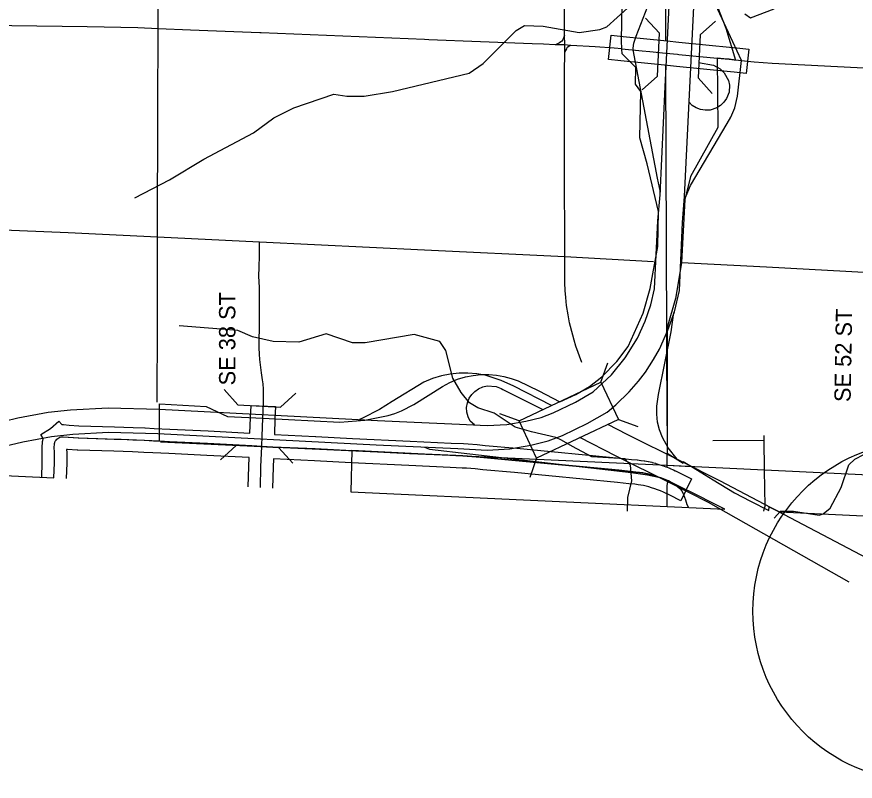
# Model space of a CAD drawing. Extents: x -1403959 to 81668, y -1400582 to 11018.
# Drawn here: x 7536.2 to 7735.1, y 7653.3 to 7834.6 of the extents above; entities that cross this region are included whole.
import ezdxf

# ---------------------------------------------------------------- set-up
doc = ezdxf.new("R2010")
doc.units = 0
for name, color, linetype in [('tdCiCityStreetTxt', 7, 'Continuous'), ('tdCiCoBndryTxt', 7, 'Continuous'), ('tdCiMapCityName', 7, 'Continuous'), ('tdCiMapFrame', 7, 'Continuous'), ('tdCiRRCL', 7, 'Continuous'), ('tdCiRROwnerTxt', 7, 'Continuous'), ('tdCiSectLine', 7, 'Continuous'), ('tdCiSectNmbr', 7, 'Continuous'), ('tdCiSectTwpRng', 7, 'Continuous'), ('tdCiUABTitleFrame', 7, 'Continuous'), ('tdCoCityStreetMajor', 7, 'Continuous'), ('tdCoCityStreetMinor', 7, 'Continuous'), ('tdCoClipBndry', 7, 'Continuous'), ('tdCoDivCarto', 7, 'Continuous'), ('tdCoIntCL', 7, 'Continuous'), ('tdCoSectNmbr', 7, 'Continuous'), ('tdCoSurfAsphalt', 7, 'Continuous'), ('tdCoSurfBitum', 7, 'Continuous'), ('tdCoSurfEarth', 7, 'Continuous')]:
    doc.layers.add(name, color=color, linetype=linetype)

msp = doc.modelspace()

# ---------------------------------------------------------------- linework, layer by layer
at = {"layer": 'tdCiCityStreetTxt'}
for p, q in [((7674.73, 7747.9), (7676.37, 7752.49)), ((7655.34, 7738.74), (7674.73, 7747.9)), ((7674.73, 7747.9), (7678.89, 7739.09)), ((7655.34, 7738.74), (7650.75, 7740.38)), ((7659.5, 7729.92), (7655.34, 7738.74)), ((7678.89, 7739.09), (7659.5, 7729.92)), ((7678.89, 7739.09), (7683.48, 7737.44)), ((7659.5, 7729.92), (7657.86, 7725.34)), ((7659.5, 7729.92), (7659.5, 7729.92))]:
    msp.add_line(p, q, dxfattribs=at)
at = {"layer": 'tdCiCoBndryTxt'}
msp.add_lwpolyline([(7594.29, 7732.76), (7594.37, 7735.11), (7594.54, 7739.36)], dxfattribs=at)
at = {"layer": 'tdCiMapCityName'}
for points in [[(7545, 7725.21), (7545.13, 7728.81), (7545.13, 7731.18), (7545.1, 7732.59), (7545.15, 7733.06), (7545.17, 7733.35), (7545.23, 7733.64), (7545.34, 7733.91), (7545.5, 7734.17), (7545.68, 7734.4), (7545.9, 7734.58)], [(7545.91, 7734.59), (7546.16, 7734.75), (7546.43, 7734.86), (7546.72, 7734.94), (7547.01, 7734.96), (7548.41, 7734.84), (7550.75, 7734.68), (7559.27, 7734.44), (7560.97, 7734.38)]]:
    msp.add_lwpolyline(points, dxfattribs=at)
at = {"layer": 'tdCiMapFrame'}
for points in [[(7560.97, 7734.38), (7563.72, 7734.28), (7566.48, 7734.17), (7568.62, 7734.04), (7570.04, 7733.98)], [(7570.04, 7733.98), (7570.05, 7733.98), (7572.41, 7733.88), (7581.46, 7733.45), (7591.92, 7732.9), (7594.29, 7732.76), (7594.32, 7732.76)], [(7593.97, 7722.92), (7594.12, 7727.86), (7594.29, 7732.69)], [(7594.29, 7732.69), (7594.29, 7732.76)], [(7594.32, 7732.76), (7596.96, 7732.61), (7606.95, 7732.15), (7615.66, 7731.68)], [(7615.66, 7731.68), (7629.35, 7731.04), (7639.1, 7730.59), (7640.32, 7730.53)], [(7640.32, 7730.53), (7642, 7730.45), (7643.01, 7730.39), (7643.08, 7730.38), (7645.16, 7730.22), (7647.01, 7730.05), (7654.53, 7729.35), (7678.97, 7727.03), (7681.67, 7726.73), (7683.07, 7726.58), (7683.92, 7726.49), (7684.67, 7726.39), (7685.43, 7726.25), (7686.17, 7726.08), (7686.91, 7725.88), (7687.64, 7725.64), (7688.43, 7725.4), (7689.21, 7725.12), (7689.99, 7724.82), (7690.75, 7724.49)], [(7690.75, 7724.49), (7691.17, 7724.29), (7692.38, 7723.69)]]:
    msp.add_lwpolyline(points, dxfattribs=at)
at = {"layer": 'tdCiRRCL'}
for p, q in [((7615.46, 7721.92), (7704.18, 7717.77)), ((7717.09, 7717.17), (7738.73, 7716.16))]:
    msp.add_line(p, q, dxfattribs=at)
for points in [[(7699.01, 7845.73), (7704.39, 7831.87), (7706.67, 7824.31), (7705.14, 7824.48), (7704.73, 7824.52), (7702.36, 7824.75), (7702.47, 7808.29), (7696.01, 7796.68), (7694.65, 7791.25), (7693.9, 7776.27), (7693.81, 7775.76), (7692.45, 7767.77), (7690.43, 7760.86), (7690.49, 7732.61), (7690.49, 7731.09), (7694.29, 7728.69), (7694.29, 7729.09), (7696.24, 7727.9), (7701.34, 7724.73), (7706.43, 7721.64), (7710.25, 7719.71), (7714.62, 7717.51), (7714.63, 7718.38), (7717.09, 7717.17)], [(7545, 7725.21), (7545.13, 7728.81), (7545.13, 7731.18), (7545.1, 7732.59), (7545.15, 7733.06), (7545.17, 7733.35), (7545.23, 7733.64), (7545.34, 7733.91), (7545.5, 7734.17), (7545.68, 7734.39), (7545.91, 7734.59), (7546.16, 7734.75), (7546.4, 7734.85), (7546.75, 7734.94), (7547.17, 7734.94), (7550.95, 7734.68), (7557.63, 7734.52), (7560.97, 7734.39), (7570.04, 7733.98), (7570.06, 7738.6), (7570.07, 7742.8), (7581.15, 7742.12), (7586.19, 7739.8), (7594.56, 7739.36), (7612.81, 7738.42), (7618.75, 7738.92), (7624.29, 7740.02), (7625.86, 7740.47), (7627.46, 7741.1), (7630.34, 7742.59), (7637.19, 7746.91), (7638.92, 7747.84), (7640.77, 7748.6), (7642.61, 7749.15), (7644.43, 7749.51), (7646.27, 7749.71), (7648.13, 7749.73), (7649.98, 7749.58), (7651.76, 7749.28), (7653.45, 7748.82), (7655.09, 7748.22), (7660, 7745.83), (7665.02, 7743.28), (7668.84, 7744.96), (7672.05, 7746.86), (7674.96, 7749.15), (7678.5, 7752.81), (7681.25, 7756.36), (7684.76, 7764.31), (7686.46, 7770.15), (7688.24, 7780.07), (7688.43, 7788.37), (7685.76, 7799.73), (7683.95, 7805.87), (7684.22, 7816.87), (7682.98, 7818.57), (7683.06, 7822.51), (7679.78, 7825.76), (7679.74, 7826.89), (7679.66, 7828.92), (7679.78, 7837.61)], [(7704.18, 7717.77), (7700.99, 7719.36), (7697.73, 7721.04), (7693.06, 7723.35), (7691.17, 7724.29), (7690.75, 7724.49), (7689.99, 7724.82), (7689.21, 7725.12), (7688.43, 7725.4), (7687.64, 7725.64), (7686.91, 7725.88), (7686.17, 7726.08), (7685.43, 7726.25), (7684.67, 7726.39), (7683.92, 7726.49), (7683.07, 7726.58), (7681.77, 7726.72), (7678.97, 7727.03), (7654.53, 7729.35), (7647.01, 7730.05), (7645.16, 7730.22), (7643.08, 7730.38), (7642, 7730.45), (7640.32, 7730.52), (7632.94, 7730.86), (7615.66, 7731.68), (7615.46, 7721.92)], [(7305.6, 7729.16), (7498.06, 7727.41), (7545, 7725.21)]]:
    msp.add_lwpolyline(points, dxfattribs=at)
at = {"layer": 'tdCiRROwnerTxt'}
for points in [[(7679.75, 7827), (7684.57, 7826.51), (7684.57, 7826.51)], [(7684.57, 7826.51), (7686.35, 7826.33), (7690.15, 7825.96), (7692.95, 7825.67), (7693.23, 7825.65)], [(7693.23, 7825.65), (7702.36, 7824.76)], [(7702.36, 7824.76), (7705.14, 7824.48)], [(7702.36, 7824.76), (7702.36, 7824.76)], [(7705.14, 7824.48), (7705.14, 7824.48), (7705.79, 7824.42), (7706.35, 7824.36), (7706.66, 7824.32)]]:
    msp.add_lwpolyline(points, dxfattribs=at)
at = {"layer": 'tdCiSectLine'}
for points in [[(7709.22, 7821.11), (7706.33, 7821.44), (7705.48, 7821.54), (7692.67, 7822.79), (7692.65, 7822.79), (7689.86, 7823.08), (7684.29, 7823.62), (7684.27, 7823.62), (7679.45, 7824.12), (7676.57, 7824.42), (7677.16, 7830.19), (7680.05, 7829.89), (7684.86, 7829.39), (7690.43, 7828.85), (7690.45, 7828.85), (7693.24, 7828.56), (7706.07, 7827.31), (7706.11, 7827.31), (7706.98, 7827.21), (7709.87, 7826.88), (7709.22, 7821.11)], [(7542.1, 7725.35), (7542.23, 7728.86), (7542.23, 7731.15), (7542.2, 7732.53), (7542.2, 7732.59), (7542.21, 7732.78), (7542.22, 7732.89), (7542.26, 7733.3), (7542.27, 7733.54), (7542.27, 7733.54), (7542.29, 7733.73), (7542.32, 7733.92), (7542.34, 7733.99), (7542.4, 7734.28), (7542.43, 7734.39), (7542.49, 7734.57), (7542.49, 7734.57), (7541.91, 7735.5), (7544.17, 7736.92), (7546.17, 7738.68), (7546.88, 7737.86), (7547.01, 7737.87), (7547.2, 7737.86), (7547.27, 7737.85), (7548.64, 7737.73), (7550.89, 7737.58), (7559.35, 7737.34), (7559.38, 7737.34), (7563.83, 7737.18), (7563.84, 7737.18), (7566.59, 7737.07), (7566.65, 7737.07), (7568.77, 7736.94), (7572.53, 7736.78), (7572.54, 7736.78), (7581.59, 7736.35), (7581.61, 7736.35), (7591.5, 7735.82), (7591.64, 7739.48), (7591.76, 7742.38), (7597.56, 7742.15), (7597.44, 7739.25), (7597.29, 7735.5), (7607.08, 7735.05), (7607.1, 7735.05), (7615.8, 7734.58), (7629.49, 7733.93), (7639.23, 7733.49), (7639.25, 7733.49), (7642.14, 7733.35), (7642.17, 7733.34), (7643.25, 7733.28), (7643.27, 7733.28), (7643.3, 7733.28), (7645.38, 7733.12), (7645.43, 7733.11), (7647.28, 7732.94), (7654.8, 7732.24), (7654.8, 7732.24), (7679.24, 7729.92), (7679.29, 7729.91), (7681.98, 7729.61), (7683.37, 7729.47), (7683.4, 7729.47), (7684.24, 7729.37), (7684.29, 7729.36), (7684.3, 7729.36), (7685.05, 7729.26), (7685.18, 7729.24), (7685.94, 7729.11), (7685.99, 7729.1), (7686.07, 7729.08), (7686.81, 7728.91), (7686.92, 7728.89), (7686.94, 7728.88), (7687.68, 7728.68), (7687.81, 7728.64), (7688.52, 7728.41), (7689.29, 7728.17), (7689.36, 7728.15), (7689.39, 7728.13), (7690.17, 7727.86), (7690.27, 7727.82), (7691.04, 7727.52), (7691.1, 7727.5), (7691.14, 7727.48), (7691.9, 7727.15), (7691.97, 7727.12), (7692.39, 7726.92), (7692.45, 7726.9), (7692.46, 7726.89), (7693.67, 7726.29), (7696.27, 7725), (7693.69, 7719.8), (7691.09, 7721.09), (7689.91, 7721.68), (7689.56, 7721.84), (7688.88, 7722.14), (7688.2, 7722.4), (7687.51, 7722.64), (7686.77, 7722.87), (7686.74, 7722.88), (7686.08, 7723.1), (7685.47, 7723.27), (7684.85, 7723.41), (7684.23, 7723.52), (7683.56, 7723.61), (7682.76, 7723.7), (7681.38, 7723.84), (7681.35, 7723.84), (7678.67, 7724.14), (7654.26, 7726.46), (7646.74, 7727.16), (7646.73, 7727.16), (7644.91, 7727.33), (7642.88, 7727.49), (7641.84, 7727.55), (7638.96, 7727.69), (7629.22, 7728.14), (7629.22, 7728.14), (7615.52, 7728.78), (7615.5, 7728.78), (7606.8, 7729.25), (7597.09, 7729.7), (7597.02, 7727.77), (7596.87, 7722.79)], [(7591.07, 7723.06), (7591.22, 7727.95), (7591.22, 7727.96), (7591.29, 7730.02), (7581.31, 7730.55), (7572.28, 7730.98), (7568.5, 7731.14), (7568.45, 7731.14), (7566.33, 7731.27), (7563.61, 7731.38), (7559.18, 7731.54), (7550.67, 7731.78), (7550.56, 7731.78), (7550.55, 7731.78), (7548.21, 7731.94), (7548.15, 7731.95), (7548.02, 7731.96), (7548.04, 7731.24), (7548.04, 7731.18), (7548.04, 7728.81), (7548.03, 7728.7), (7547.9, 7725.08)]]:
    msp.add_lwpolyline(points, dxfattribs=at)
at = {"layer": 'tdCiSectNmbr'}
for points in [[(7569.74, 7831.81), (7569.64, 7854.91)], [(7408.49, 7834.37), (7460.06, 7833.6), (7476.35, 7833.38), (7499.12, 7832.97), (7552.93, 7832.28), (7564.93, 7832.04), (7569.74, 7831.81), (7577.39, 7831.49), (7593.85, 7830.85), (7594.2, 7830.83), (7632.94, 7829.26), (7633.96, 7829.21), (7658.41, 7828.25), (7661.1, 7828.14)], [(7661.1, 7828.14), (7663.91, 7828.02), (7663.99, 7828.02)], [(7663.99, 7828.02), (7664.15, 7828.01), (7666.19, 7827.95)], [(7666.19, 7827.95), (7667.49, 7827.85), (7667.59, 7827.84), (7673.42, 7827.55), (7677.86, 7827.2), (7679.73, 7827.01)], [(7706.67, 7824.32), (7708.78, 7824.08), (7711.14, 7823.87), (7715.34, 7823.57)], [(7715.34, 7823.57), (7738.64, 7822.36), (7738.67, 7822.36)], [(7692.39, 7723.68), (7693.03, 7723.13), (7693.44, 7722.73), (7693.92, 7722.16), (7694.35, 7721.28), (7694.79, 7720), (7695.16, 7718.88), (7695.54, 7718.18)]]:
    msp.add_lwpolyline(points, dxfattribs=at)
at = {"layer": 'tdCiSectTwpRng'}
for points in [[(7666.12, 7834.04), (7666.12, 7834.04), (7666.08, 7838.51)], [(7666.1, 7830.95), (7666.1, 7830.95), (7666.12, 7834.04)], [(7569.59, 7782.42), (7569.68, 7812.79), (7569.74, 7831.8)], [(7569.74, 7831.8), (7569.74, 7831.81)], [(7666.12, 7830.23), (7665.73, 7829.1), (7665.48, 7828.81), (7665.26, 7828.6), (7664.91, 7828.4), (7664.15, 7828.01)], [(7666.19, 7827.95), (7666.19, 7827.95), (7666.12, 7830.23), (7666.1, 7830.95)], [(7666.19, 7825.3), (7666.19, 7825.3), (7666.19, 7826.15), (7666.19, 7827.95)], [(7666.19, 7826.15), (7666.67, 7827), (7666.78, 7827.26), (7666.93, 7827.44), (7667.49, 7827.85)], [(7666.13, 7822.21), (7666.19, 7825.3)], [(7666.13, 7799.87), (7666.13, 7799.87), (7666.13, 7822.21)], [(7670.2, 7752.62), (7668.84, 7756.49), (7668.41, 7757.89), (7668.07, 7759.07), (7667.33, 7762.01), (7667, 7763.86), (7666.61, 7766.07), (7666.4, 7768.02), (7666.31, 7769.63), (7666.19, 7771.51), (7666.22, 7777.68), (7666.13, 7799.87)], [(7498.85, 7785.26), (7516.67, 7784.66), (7523.36, 7784.41), (7548.36, 7783.38), (7569.59, 7782.42)], [(7569.47, 7743.19), (7569.54, 7761.66), (7569.59, 7782.42)], [(7569.59, 7782.42), (7593.75, 7781.23), (7632.87, 7779.33), (7666.22, 7777.68)], [(7594.54, 7739.36), (7594.61, 7741.16), (7594.72, 7743.08), (7594.74, 7744.86), (7594.71, 7746.26), (7594.61, 7747.55), (7594.49, 7748.49), (7594.22, 7750.17), (7593.83, 7753.26), (7593.77, 7754.53), (7593.69, 7756.06), (7593.69, 7757.3), (7593.74, 7761.37), (7593.77, 7767.92), (7593.74, 7770.4), (7593.64, 7773.09), (7593.69, 7775.16), (7593.74, 7777.91), (7593.75, 7781.23)], [(7666.22, 7777.68), (7687.21, 7776.56)], [(7693.9, 7776.27), (7714, 7775.24), (7738.63, 7773.96), (7738.73, 7773.96)], [(7713.53, 7727.11), (7713.53, 7727.13), (7713.47, 7734.13), (7713.47, 7735.28)], [(7701.32, 7734.08), (7713.41, 7734.13)], [(7713.41, 7734.13), (7713.47, 7734.13)], [(7713.53, 7727.09), (7713.53, 7727.11)], [(7713.58, 7718.08), (7713.7, 7718.54), (7713.53, 7727.09)], [(7690.44, 7718.41), (7690.47, 7723.28), (7690.53, 7723.93), (7690.75, 7724.49)], [(7713.57, 7718.04), (7713.58, 7718.07)], [(7713.58, 7718.07), (7713.58, 7718.08)]]:
    msp.add_lwpolyline(points, dxfattribs=at)
at = {"layer": 'tdCiUABTitleFrame'}
msp.add_lwpolyline([(7713.39, 7717.34), (7713.57, 7718.04)], dxfattribs=at)
at = {"layer": 'tdCoCityStreetMajor'}
for points in [[(7690.12, 7828.87), (7690.18, 7897.37)], [(7690.44, 7737.57), (7690.13, 7823.04)], [(7690.48, 7728.22), (7690.47, 7731.09)], [(7688.74, 7728.3), (7690.48, 7728.22)], [(7690.47, 7727.73), (7690.48, 7728.22)], [(7690.48, 7728.22), (7696.13, 7727.95)]]:
    msp.add_lwpolyline(points, dxfattribs=at)
at = {"layer": 'tdCoCityStreetMinor'}
msp.add_lwpolyline([(7688.74, 7728.3), (7690.48, 7728.22), (7696.13, 7727.95)], dxfattribs=at)
at = {"layer": 'tdCoClipBndry'}
msp.add_lwpolyline([(7570.28, 7733.79), (7594.28, 7732.69), (7690.48, 7728.22), (7741.62, 7725.76), (7787.16, 7723.57), (7826.33, 7721.37)], dxfattribs=at)
at = {"layer": 'tdCoDivCarto'}
for points in [[(7529.92, 7737.91), (7536.48, 7739.48), (7543.61, 7740.78), (7548.94, 7741.37), (7557.88, 7741.84), (7569.94, 7741.51), (7621.72, 7738.86), (7630.48, 7738.43), (7641.18, 7737.96), (7647.77, 7737.61), (7652.46, 7737.86), (7656.93, 7738.64), (7660.55, 7739.56), (7663.41, 7740.61), (7668.72, 7743.2), (7672.88, 7745.6), (7677.27, 7749.62), (7680.54, 7753.66), (7683.46, 7758.39), (7685.26, 7762.36), (7686.61, 7766.23), (7687.5, 7770.04), (7688.28, 7786.17), (7688.82, 7792.35), (7690.02, 7817.94), (7691.27, 7843.66)], [(7531.54, 7732.34), (7537.66, 7733.79), (7544.43, 7735.04), (7549.46, 7735.59), (7557.96, 7736.04), (7569.68, 7735.72), (7621.43, 7733.06), (7640.85, 7732.17), (7647.81, 7731.8), (7653.17, 7732.09), (7658.14, 7732.96), (7662.27, 7734.01), (7665.66, 7735.25), (7671.49, 7738.09), (7676.2, 7740.82), (7678.29, 7742.55), (7681.49, 7745.63), (7683.66, 7748.17), (7685.29, 7750.31), (7687.25, 7753.33), (7688.63, 7755.72), (7690.66, 7760.23), (7692.18, 7764.6), (7693.38, 7769.64), (7694.07, 7785.77), (7694.61, 7791.98), (7695.81, 7817.69), (7697.07, 7843.41)], [(7737.95, 7706.07), (7702.94, 7724.56), (7693.74, 7729.21), (7680.99, 7735.53), (7676.37, 7737.9)], [(7733.65, 7700.52), (7700.3, 7719.39), (7690.97, 7724.1), (7678.39, 7730.34), (7669.76, 7734.77)]]:
    msp.add_lwpolyline(points, dxfattribs=at)
at = {"layer": 'tdCoIntCL'}
for points in [[(7688.85, 7792.98), (7688.16, 7796.27), (7682.37, 7826.72), (7682.37, 7827.08), (7682.53, 7828.28), (7683.08, 7829.98), (7686.42, 7838.52), (7687.1, 7840.27), (7690.76, 7849.75), (7691.61, 7852.98)], [(7694.54, 7791.15), (7696.02, 7794.57), (7704.7, 7809.24), (7705.57, 7810.76), (7706.54, 7812.96), (7707.18, 7815.71), (7708.09, 7824.19), (7700.87, 7839.73), (7699.13, 7844.1), (7697.46, 7850.02), (7697.33, 7850.73)], [(7697.89, 7823.74), (7701.49, 7823.08), (7703.01, 7822.25), (7703.98, 7821.3), (7704.99, 7819.47), (7705.24, 7818.34), (7705.14, 7816.71), (7704.56, 7815.18), (7703.94, 7814.29), (7703.15, 7813.53), (7702.23, 7812.95), (7700.65, 7812.45), (7699.48, 7812.39), (7698.41, 7812.55), (7697.36, 7812.95), (7696.4, 7813.56), (7695.66, 7814.32)], [(7692.86, 7729.64), (7690.68, 7732.33), (7689.33, 7734.83), (7688.66, 7736.61), (7688.21, 7738.46), (7687.99, 7740.35), (7688, 7742.26), (7688.39, 7745.01), (7691.41, 7759.86), (7692.06, 7764.41)], [(7663.07, 7742.38), (7654.06, 7746.97), (7651.1, 7748.34), (7647.32, 7749.54), (7645.31, 7749.89), (7643.21, 7750.06), (7641.1, 7750.03), (7639, 7749.81), (7636.93, 7749.39), (7634.84, 7748.77), (7632.75, 7747.92), (7625.22, 7743.33), (7622.2, 7741.44), (7618.24, 7739.4), (7617.46, 7739.08)], [(7644.78, 7737.77), (7643.73, 7738.64), (7643.23, 7739.66), (7642.95, 7740.77), (7642.9, 7741.9), (7643.08, 7743.02), (7643.49, 7744.09), (7644.1, 7744.97), (7644.86, 7745.73), (7645.74, 7746.34), (7646.72, 7746.78), (7647.76, 7747.03), (7649.87, 7746.86), (7651.08, 7746.39), (7651.51, 7746.18), (7660.97, 7741.4)], [(7632.9, 7732.54), (7634.12, 7732.01), (7681.89, 7726.47), (7685.79, 7725.96), (7688.39, 7725.38)]]:
    msp.add_lwpolyline(points, dxfattribs=at)
at = {"layer": 'tdCoSurfAsphalt'}
msp.add_circle((7751.13, 7693.62), 40.33, dxfattribs=at)
at = {"layer": 'tdCoSurfBitum'}
for points in [[(7564.2, 7791.65), (7572.45, 7795.92), (7580.55, 7800.8), (7592.31, 7807.05), (7597.2, 7810.56), (7601.93, 7813), (7611.4, 7816.2), (7614.46, 7815.74), (7618.58, 7815.74), (7625.3, 7816.81), (7643.48, 7821.22), (7646.84, 7823.51), (7654.63, 7831.29), (7656.62, 7832.51), (7661.05, 7832.36), (7669.6, 7830.82), (7674.49, 7831.58), (7676.17, 7832.19), (7683.5, 7838.91)], [(7708.85, 7835.23), (7710.23, 7834.31), (7715.88, 7836.44)], [(7681.05, 7717.34), (7681.16, 7720.57), (7682.08, 7724.54), (7681.77, 7728.2), (7680.4, 7729.73), (7672.61, 7730.2), (7668.03, 7732.64), (7665.43, 7734.17), (7664.06, 7734.78), (7658.26, 7736.16), (7654.44, 7737.23), (7649.4, 7740.59), (7645.58, 7741.82), (7643.6, 7743.04), (7641.61, 7745.49), (7639.63, 7748.85), (7637.95, 7755.41), (7636.58, 7757.55), (7630.47, 7759.24), (7618.86, 7757.26), (7615.81, 7757.26), (7609.55, 7759.4), (7603.13, 7757.42), (7597.02, 7757.58), (7592.13, 7758.65), (7588.62, 7760.18), (7574.72, 7761.26)], [(7715.85, 7715.69), (7717.37, 7717.32), (7720.42, 7717.32), (7726.54, 7716.39), (7727.45, 7716.7), (7729.13, 7718.07), (7731.73, 7722.95), (7733.57, 7728.29), (7734.95, 7729.66), (7737.09, 7730.73)]]:
    msp.add_lwpolyline(points, dxfattribs=at)
at = {"layer": 'tdCoSurfEarth'}
for p, q in [((7688.64, 7830.65), (7685.36, 7834.26)), ((7698.31, 7830.26), (7701.92, 7833.54)), ((7688.14, 7820.49), (7688.64, 7830.65)), ((7698.31, 7830.26), (7697.81, 7820.09)), ((7688.14, 7820.49), (7684.53, 7817.21)), ((7697.81, 7820.09), (7701.15, 7816.4)), ((7588.63, 7742.54), (7585.36, 7746.16)), ((7598.78, 7742.02), (7602.4, 7745.29)), ((7588.63, 7742.54), (7598.78, 7742.02)), ((7588.2, 7732.88), (7584.51, 7729.54)), ((7598.38, 7732.35), (7588.2, 7732.88)), ((7598.38, 7732.35), (7601.64, 7728.73))]:
    msp.add_line(p, q, dxfattribs=at)

# ---------------------------------------------------------------- texts
at = {"layer": 'tdCoSectNmbr'}
for s, rotation, p in [('SE 38 ST', 90, (7588.04, 7747.15)), ('SE 52 ST', 89, (7733.98, 7743.18))]:
    msp.add_text(s, height=3.869, rotation=rotation, dxfattribs=at).set_placement(p)

doc.saveas('drawing.dxf')
